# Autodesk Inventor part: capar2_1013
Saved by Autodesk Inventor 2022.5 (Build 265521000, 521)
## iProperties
Created: 2024-12
Part Number: capar2_1013
Material: Generic
Document SubType Name: Modeling
Designer: AdminForWorker
Density: 1 g/cm^3
Appearance: Default
Title: capar2_1013 v1
Author: AdminForWorker
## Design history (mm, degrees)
feature "Body22"
feature "Body39"
feature "Body40"
feature "Body41"
feature "Body42"
body "Solid1"
body "Solid2"
body "Solid3"
body "Solid4"
body "Solid5"
